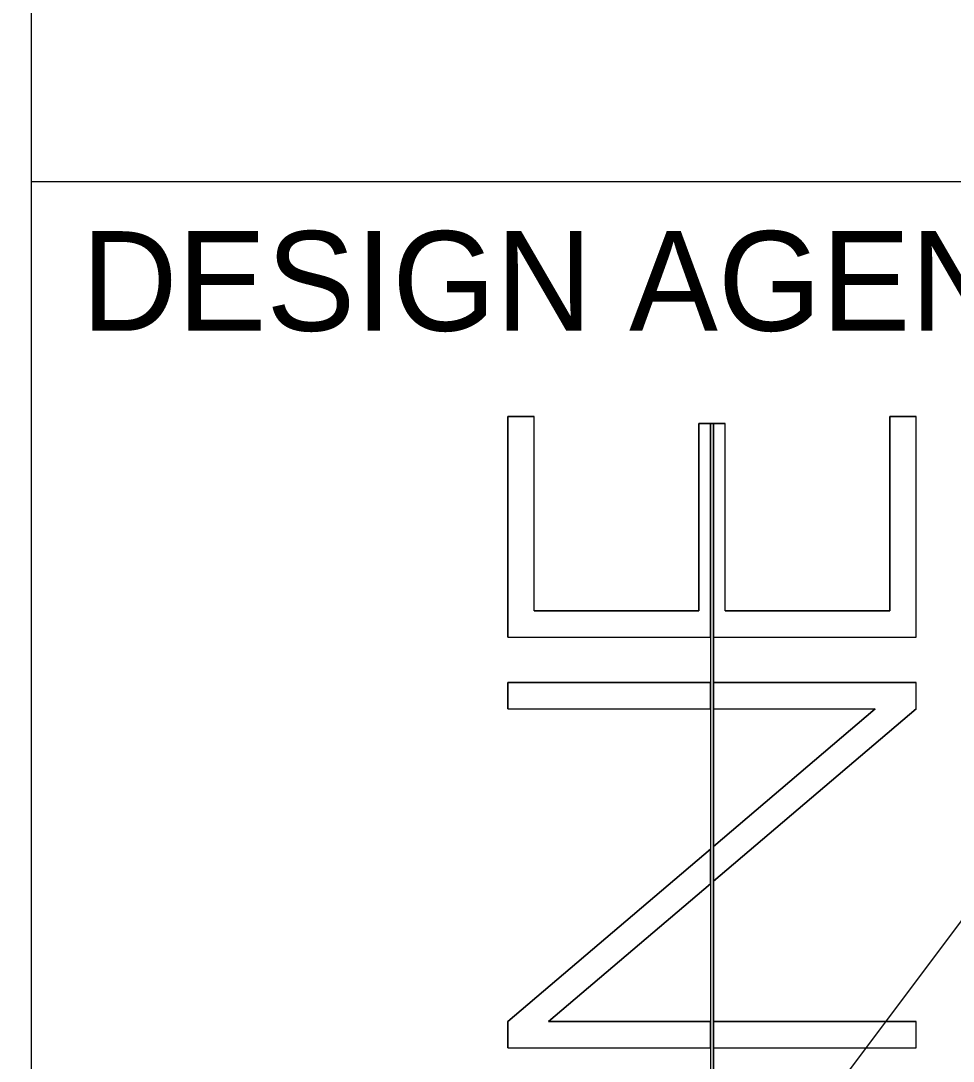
# Model space of a CAD drawing. Extents: x 0 to 128, y -9 to 33.
# Drawn here: x 31.989 to 32.925, y 4.117 to 5.161 of the extents above; entities that cross this region are included whole.
import ezdxf

# ---------------------------------------------------------------- set-up
doc = ezdxf.new("R2010")
doc.units = 0
for name, color, linetype in [('GE_X_Alignment_1000_Stations', 7, 'Continuous'), ('GE_X_Alignment_100_Curve_Data', 7, 'Continuous'), ('GE_X_Alignment_100_Stations', 7, 'Continuous')]:
    doc.layers.add(name, color=color, linetype=linetype)

msp = doc.modelspace()

# ---------------------------------------------------------------- linework, layer by layer
at = {"layer": 'GE_X_Alignment_1000_Stations'}
msp.add_line((31.9892, 2.9987), (33.4892, 4.9987), dxfattribs=at)
at = {"layer": 'GE_X_Alignment_100_Curve_Data'}
for p, q in [((32.4782, 4.7639), (32.5045, 4.7639)), ((32.4782, 4.5426), (32.4782, 4.7639)), ((32.5045, 4.5689), (32.5045, 4.7639)), ((32.8616, 4.7639), (32.888, 4.7639)), ((32.8616, 4.5689), (32.8616, 4.7639)), ((32.888, 4.5426), (32.888, 4.7639)), ((32.6699, 4.5689), (32.6699, 4.7568)), ((32.6699, 4.7568), (32.6815, 4.7568)), ((32.6815, 4.7568), (32.6815, 3.9718)), ((32.6815, 4.7568), (32.6815, 4.5426)), ((32.6815, 4.7568), (32.6847, 4.7568)), ((32.6847, 4.7568), (32.6847, 3.9718)), ((32.6847, 4.7568), (32.6847, 4.5426)), ((32.6847, 4.7568), (32.6963, 4.7568)), ((32.6963, 4.5689), (32.6963, 4.7568)), ((32.5045, 4.5689), (32.6699, 4.5689)), ((32.6963, 4.5689), (32.8616, 4.5689)), ((32.4782, 4.5426), (32.6815, 4.5426)), ((32.6847, 4.5426), (32.888, 4.5426)), ((32.4782, 4.4705), (32.4782, 4.4968)), ((32.4782, 4.4968), (32.6815, 4.4968)), ((32.6815, 4.4968), (32.6815, 4.4705)), ((32.6847, 4.4968), (32.6847, 4.4705)), ((32.6847, 4.4968), (32.888, 4.4968)), ((32.888, 4.4705), (32.888, 4.4968)), ((32.4782, 4.4705), (32.6815, 4.4705)), ((32.6847, 4.3324), (32.847, 4.4705)), ((32.888, 4.4705), (32.6847, 4.2976)), ((32.6847, 4.4705), (32.847, 4.4705)), ((32.4782, 4.1567), (32.6815, 4.3297)), ((32.6815, 4.3297), (32.6815, 4.2949)), ((32.6847, 4.3324), (32.6847, 4.2976)), ((32.6815, 4.2949), (32.5189, 4.1567)), ((32.4782, 4.1303), (32.4782, 4.1567)), ((32.5189, 4.1567), (32.6815, 4.1567)), ((32.6815, 4.1567), (32.6815, 4.1303)), ((32.6847, 4.1567), (32.6847, 4.1303)), ((32.6847, 4.1567), (32.888, 4.1567)), ((32.888, 4.1303), (32.888, 4.1567)), ((32.4782, 4.1303), (32.6815, 4.1303)), ((32.6847, 4.1303), (32.888, 4.1303))]:
    msp.add_line(p, q, dxfattribs=at)
for points in [[(32.4782, 4.7639), (32.4782, 4.5426), (32.6815, 4.5426), (32.6815, 4.7568), (32.6699, 4.7568), (32.6699, 4.5689), (32.5045, 4.5689), (32.5045, 4.7639)], [(32.6963, 4.5689), (32.6963, 4.7568), (32.6847, 4.7568), (32.6847, 4.5426), (32.888, 4.5426), (32.888, 4.7639), (32.8616, 4.7639), (32.8616, 4.5689)], [(32.4782, 4.4968), (32.4782, 4.4705), (32.6815, 4.4705), (32.6815, 4.4968)], [(32.6847, 4.4968), (32.6847, 4.4705), (32.847, 4.4705), (32.6847, 4.3324), (32.6847, 4.2976), (32.888, 4.4705), (32.888, 4.4968)], [(32.4782, 4.1567), (32.4782, 4.1303), (32.6815, 4.1303), (32.6815, 4.1567), (32.5189, 4.1567), (32.6815, 4.2949), (32.6815, 4.3297)], [(32.6847, 4.1567), (32.6847, 4.1303), (32.888, 4.1303), (32.888, 4.1567)]]:
    msp.add_lwpolyline(points, close=True, dxfattribs=at)
msp.add_lwpolyline([(32.8209, 3.9673), (32.6878, 3.9344), (32.6878, 3.9718), (32.6847, 3.9718), (32.6847, 4.7568), (32.6815, 4.7568), (32.6815, 3.9718), (32.6784, 3.9718), (32.6784, 3.932), (32.6041, 3.9136)], dxfattribs=at)
at = {"layer": 'GE_X_Alignment_100_Stations'}
for p, q in [((32, 0.5), (32, 21.5)), ((32, 5), (33.5, 5))]:
    msp.add_line(p, q, dxfattribs=at)

# ---------------------------------------------------------------- texts
at = {"layer": 'GE_X_Alignment_100_Curve_Data'}
msp.add_text('DESIGN AGENCY', height=0.1, dxfattribs=at).set_placement((32.05, 4.85))

doc.saveas('drawing.dxf')
